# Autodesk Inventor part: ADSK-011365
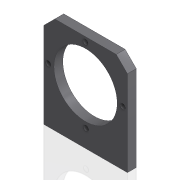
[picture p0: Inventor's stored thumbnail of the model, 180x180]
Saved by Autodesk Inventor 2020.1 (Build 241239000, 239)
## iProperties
Created: 1999-12
Part Number: ADSK-011365
Material: Acier doux
Document SubType Name: Modeling
Designer: sspink
Density: 7.86 g/cm^3
Appearance: Metal-Steel(Polish)
Mass: 410.964 g
Surface Area: 172.335 cm^2
Volume: 52.2854 cm^3
Control State: 0
Checked Out: False
Master: False
Shininess: 0.0
Length Units: 11269
Angle Units: 11279
Time Units: 11290
Mass Units: 11283
Length Display Precision: 5
Angle Display Precision: 2
Compacted: True
Dimensions: 90x104x9,5 mm
Mass: 0,411 kg
DocNumber: ADSK-011365.ipt
Folder: 01 - Themengebiete\Simplification\01 - Packaging machine\
VDS_Category: 3D Komponenten
Density: 0.0
Volumn: 0.0
Area: 0.0
PropertySet Name: Model Information
Author: sspink
Revision Number: -
Title: plate
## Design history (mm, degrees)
node "Solide1"
  node "Extrusion1" dims "d5" = 9.525, "d6" = 0
  node "Hole1" dims "d16" = 5.5, "d17" = 9.525, "d18" = 6.35, "d19" = 60 deg, "d20" = 19.05, "d21" = 118 deg, "d31" = 6
  node "Chamfer1" dims "d22" = 12, "d23" = 12, "d28" = 45 deg
sketch "Sketch1"
  geometry: L1 (-45, 45)-(45, 45); L2 (45, 45)-(45, -59); L3 (45, -59)-(-45, -59); L4 (-45, -59)-(-45, 45); C1 r 34 at (0, 0); 2 further points
  constraints: 8 end point, 2 parallel, 1 centre point, 1 coincident, 1 horizontal, 1 midpoint, 1 perpendicular, 1 vertical alignment
  dimensions: "d0" = 68 diameter of C1; "d3" = 45 distance from line of L1 C1.centre; "d29" = 90 distance of L1.start L1.end; "d30" = 104 distance of L1.end L2.end
sketch "Sketch2"
  geometry: L1 (45, 45)-(45, -59) reference; C1 r 34 at (0, 0) reference; A1 r 40 centre (0, 0) between (0, 40) and (-40, 0); 7 further points
  constraints: 9 coincident, 4 point on circle, 2 horizontal alignment, 1 centre point, 1 vertical alignment, 8 other
  dimensions: "d15" = 44.45 distance from line of point (0.55, -39.996) L1; "d27" = 80 diameter of A1
node "Corps solides"
node "Corps surfaciques"
